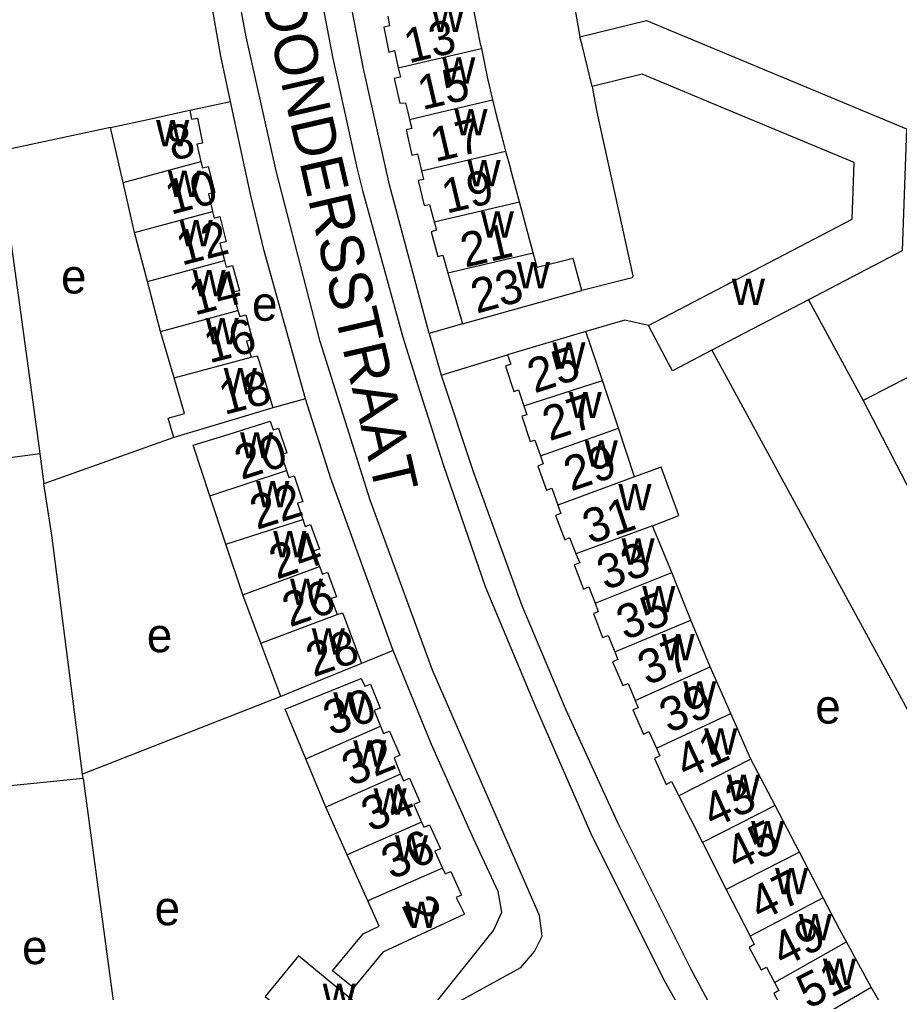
# Model space of a CAD drawing. Extents: x 161141 to 163125, y 381621 to 383200.
# Drawn here: x 162447 to 162549.8, y 382330.5 to 382444.2 of the extents above; entities that cross this region are included whole.
import ezdxf

# ---------------------------------------------------------------- set-up
doc = ezdxf.new("R2010")
doc.units = 0
for name, color, linetype in [('BLT_Basislijn', 7, 'Continuous'), ('BLT_Bebouwing', 7, 'Continuous'), ('BLT_Centroide', 7, 'Continuous'), ('BLT_Huisnummer', 7, 'Continuous'), ('BLT_Huisnummer_ tussenligend', 7, 'Continuous'), ('BLT_Onderverdeling_panden', 7, 'Continuous'), ('BLT_Straatnaam', 7, 'Continuous')]:
    doc.layers.add(name, color=color, linetype=linetype)

msp = doc.modelspace()

# ---------------------------------------------------------------- linework, layer by layer
at = {"layer": 'BLT_Basislijn'}
for p, q in [((162470.54, 382439.87), (162467.69, 382456.09)), ((162473.49, 382442.13), (162470.94, 382456.3)), ((162480.44, 382456.29), (162483.63, 382439.6)), ((162477.01, 382426.5), (162473.49, 382442.13)), ((162471.68, 382434.6), (162470.54, 382439.87)), ((162483.63, 382439.6), (162486.48, 382426.67)), ((162466.9, 382433.57), (162471.68, 382434.6)), ((162474.01, 382423.75), (162471.68, 382434.6)), ((162457.66, 382431.55), (162444.54, 382428.75)), ((162482.13, 382406.54), (162477.01, 382426.5)), ((162486.48, 382426.67), (162487.08, 382424.17)), ((162487.08, 382424.17), (162491.79, 382407.05)), ((162475.61, 382417.12), (162474.01, 382423.75)), ((162480.44, 382399.86), (162475.61, 382417.12)), ((162539.18, 382411.42), (162545.56, 382399.66)), ((162498.76, 382408.62), (162494.88, 382407.48)), ((162491.79, 382407.05), (162493.8, 382400.69)), ((162494.88, 382407.48), (162496.28, 382402.62)), ((162487.97, 382388.02), (162482.13, 382406.54)), ((162496.28, 382402.62), (162504.01, 382404.98)), ((162527.9, 382405.52), (162569.67, 382328.72)), ((162496.28, 382402.62), (162500, 382391.35)), ((162493.8, 382400.69), (162496.54, 382392.04)), ((162480.44, 382399.86), (162476.6, 382398.79)), ((162483.37, 382390.55), (162480.44, 382399.86)), ((162465.03, 382395.34), (162449.88, 382389.91)), ((162449.39, 382393.43), (162435.44, 382391.55)), ((162449.39, 382393.43), (162449.88, 382389.91)), ((162496.54, 382392.04), (162501.42, 382377.94)), ((162500, 382391.35), (162505.69, 382375.72)), ((162490.67, 382370.44), (162483.37, 382390.55)), ((162495.26, 382368.13), (162487.97, 382388.02)), ((162501.42, 382377.94), (162507.21, 382364.06)), ((162505.69, 382375.72), (162510.86, 382363.5)), ((162490.67, 382370.44), (162486.99, 382368.93)), ((162495.16, 382359.48), (162490.67, 382370.44)), ((162477.56, 382365.09), (162454.39, 382355.98)), ((162507.21, 382364.06), (162513.89, 382348.78)), ((162510.86, 382363.5), (162516.88, 382350.34)), ((162500, 382348.54), (162495.16, 382359.48)), ((162454.46, 382355.5), (162443.13, 382354.34)), ((162516.88, 382350.34), (162525.44, 382333.21)), ((162502.95, 382342.3), (162500, 382348.54)), ((162513.89, 382348.78), (162522.44, 382331.7)), ((162525.44, 382333.21), (162528.2, 382328.08)), ((162522.44, 382331.7), (162532.47, 382313.94))]:
    msp.add_line(p, q, dxfattribs=at)
for points in [[(162494.88, 382407.48), (162490.26, 382424.86), (162487.16, 382438.59), (162484.97, 382449.88), (162482.85, 382462.33), (162479.37, 382488.89), (162492.21, 382499.45), (162509.86, 382491.53)], [(162509.86, 382491.53), (162505.95, 382480.43), (162506, 382478.74), (162512.49, 382442.15)], [(162513.91, 382436.34), (162514.48, 382433.33), (162518.68, 382414.23), (162518.59, 382413.97), (162512.72, 382412.49)], [(162444.54, 382428.75), (162449.3, 382394.04), (162449.39, 382393.43)], [(162520.51, 382408.41), (162517.74, 382409.05), (162513.19, 382407.72)], [(162454.39, 382355.98), (162450.81, 382383.91), (162449.88, 382389.91)], [(162493.76, 382326.89), (162505.57, 382333.42), (162507.2, 382335.28), (162508.07, 382337.08), (162507.78, 382339.48), (162505.89, 382343.76), (162495.26, 382368.13)], [(162454.46, 382355.5), (162454.43, 382355.72), (162454.39, 382355.98)], [(162454.46, 382355.5), (162458.85, 382322.91), (162451.48, 382311.31)], [(162493.76, 382326.89), (162502.41, 382337.75), (162503.37, 382339.89), (162502.95, 382342.3)]]:
    msp.add_lwpolyline(points, dxfattribs=at)
at = {"layer": 'BLT_Bebouwing'}
for p, q in [((162500.91, 382441.14), (162500.98, 382440.79)), ((162502.27, 382434.77), (162502.62, 382433.33)), ((162459.12, 382425.13), (162457.66, 382431.55)), ((162503.8, 382428.8), (162504.38, 382426.74)), ((162505.43, 382422.85), (162504.38, 382426.74)), ((162507.04, 382416.9), (162505.43, 382422.85)), ((162461.96, 382413.57), (162460.46, 382419.28)), ((162550.15, 382417.15), (162539.18, 382411.42)), ((162497.06, 382414.55), (162498.76, 382408.62)), ((162463.49, 382407.7), (162461.96, 382413.57)), ((162539.18, 382411.42), (162527.9, 382405.52)), ((162465.07, 382402.3), (162463.49, 382407.7)), ((162513.19, 382407.72), (162504.01, 382404.98)), ((162515.11, 382402), (162513.19, 382407.72)), ((162555.87, 382405.01), (162545.56, 382399.66)), ((162474.96, 382404.34), (162476.6, 382398.79)), ((162516.98, 382396.41), (162515.11, 382402)), ((162518.88, 382390.72), (162516.98, 382396.41)), ((162471.13, 382382.86), (162469.25, 382388.52)), ((162523.24, 382379.55), (162520.95, 382385.01)), ((162473.1, 382376.93), (162471.13, 382382.86)), ((162525.46, 382373.99), (162523.24, 382379.55)), ((162475.23, 382371.29), (162473.1, 382376.93)), ((162484.97, 382374.28), (162486.99, 382368.93)), ((162527.69, 382368.54), (162525.46, 382373.99)), ((162477.56, 382365.09), (162475.23, 382371.29)), ((162532.47, 382357.75), (162530.11, 382363.08)), ((162482.79, 382352.15), (162480.46, 382357.79)), ((162524.03, 382353.47), (162526.81, 382348.01)), ((162538.14, 382346.88), (162535.31, 382352.32)), ((162526.81, 382348.01), (162529.58, 382342.54)), ((162540.91, 382341.56), (162538.14, 382346.88)), ((162487.71, 382341.2), (162485.3, 382346.57)), ((162529.58, 382342.54), (162532.36, 382337.07)), ((162546.52, 382331.1), (162543.62, 382336.42))]:
    msp.add_line(p, q, dxfattribs=at)
for points in [[(162500.91, 382441.14), (162499.95, 382446.06), (162499.79, 382446.85)], [(162490.03, 382444.55), (162490.25, 382443.42), (162489.57, 382443.28), (162490.18, 382440.36), (162490.81, 382440.53), (162491.27, 382438.51)], [(162512.49, 382442.15), (162520.27, 382444.05), (162545.96, 382433.33), (162550.65, 382431.38), (162550.15, 382417.15)], [(162513.91, 382436.34), (162512.74, 382441.16), (162512.49, 382442.15)], [(162500.98, 382440.79), (162501.7, 382437.29), (162502.27, 382434.77)], [(162491.27, 382438.51), (162491.51, 382437.42), (162490.8, 382437.27), (162491.46, 382434.38), (162492.12, 382434.44), (162492.39, 382433.33), (162492.59, 382432.49)], [(162520.51, 382408.41), (162544.3, 382420.85), (162544.53, 382427.45), (162530.41, 382433.33), (162519.77, 382437.77), (162513.91, 382436.34)], [(162457.66, 382431.55), (162462.01, 382432.5), (162465.83, 382433.33), (162466.9, 382433.57)], [(162466.9, 382433.57), (162466.94, 382433.33), (162467.1, 382432.54), (162467.8, 382432.64), (162468.4, 382429.73), (162467.72, 382429.59), (162468.21, 382427.59)], [(162502.62, 382433.33), (162503.51, 382429.87), (162503.8, 382428.8)], [(162492.59, 382432.49), (162492.85, 382431.42), (162492.18, 382431.27), (162492.85, 382428.33), (162493.5, 382428.49), (162493.97, 382426.49)], [(162468.21, 382427.59), (162468.4, 382426.82), (162469.05, 382427), (162469.82, 382423.95), (162469.08, 382423.78), (162469.57, 382421.74)], [(162493.97, 382426.49), (162494.2, 382425.49), (162493.58, 382425.34), (162494.31, 382422.43), (162494.9, 382422.57), (162495.47, 382420.51)], [(162460.46, 382419.28), (162459.12, 382425.13)], [(162469.57, 382421.74), (162469.75, 382420.96), (162470.43, 382421.15), (162471.18, 382418.18), (162470.44, 382418.03), (162470.97, 382415.99)], [(162495.47, 382420.51), (162495.73, 382419.54), (162495.1, 382419.37), (162495.9, 382416.48), (162496.47, 382416.65), (162497.06, 382414.55)], [(162512.72, 382412.49), (162511.69, 382416.24), (162507.49, 382415.21), (162507.04, 382416.9)], [(162470.97, 382415.99), (162471.16, 382415.24), (162471.91, 382415.41), (162472.7, 382412.47), (162471.95, 382412.29), (162472.54, 382410.16)], [(162498.76, 382408.62), (162500, 382408.96), (162512.72, 382412.49)], [(162472.54, 382410.16), (162472.74, 382409.45), (162473.44, 382409.66), (162474.24, 382406.7), (162473.54, 382406.57), (162474.07, 382404.73)], [(162527.9, 382405.52), (162523.29, 382403.1), (162522.83, 382403.98), (162520.51, 382408.41)], [(162474.07, 382404.73), (162474.8, 382404.87), (162474.96, 382404.34)], [(162504.01, 382404.98), (162504.4, 382403.88), (162503.8, 382403.66), (162504.77, 382400.7), (162505.32, 382400.88), (162505.94, 382399.02)], [(162465.03, 382395.34), (162464.37, 382397.6), (162466.28, 382398.15), (162465.07, 382402.3)], [(162505.94, 382399.02), (162506.28, 382397.99), (162505.71, 382397.83), (162506.68, 382394.87), (162507.24, 382395.03), (162507.88, 382393.2)], [(162545.56, 382399.66), (162553.32, 382384.69), (162551.06, 382383.52), (162555.05, 382375.82), (162557.29, 382376.98), (162570.82, 382350.91), (162569.14, 382350.04), (162575.86, 382337.08), (162579.21, 382338.82), (162580.68, 382335.99), (162581.34, 382335.17)], [(162476.6, 382398.79), (162471.81, 382397.36), (162465.03, 382395.34)], [(162469.25, 382388.52), (162467.29, 382394.42), (162471.53, 382395.71), (162476.3, 382397.23), (162476.65, 382396.24), (162477.27, 382396.42), (162478.24, 382393.55), (162477.6, 382393.3), (162478.21, 382391.47)], [(162507.88, 382393.2), (162508.21, 382392.24), (162507.59, 382392), (162508.6, 382389.18), (162509.2, 382389.4), (162509.9, 382387.41)], [(162478.21, 382391.47), (162478.48, 382390.67), (162479.11, 382390.87), (162480.11, 382387.82), (162479.49, 382387.64), (162480.13, 382385.75)], [(162520.95, 382385.01), (162524.05, 382386.2), (162523.69, 382387.18), (162521.98, 382391.88), (162518.88, 382390.72)], [(162509.9, 382387.41), (162510.24, 382386.47), (162509.65, 382386.21), (162510.73, 382383.38), (162511.27, 382383.64), (162512.03, 382381.73)], [(162480.13, 382385.75), (162480.4, 382384.93), (162481, 382385.17), (162482.06, 382382.3), (162481.41, 382382.09), (162482.08, 382380.27)], [(162512.03, 382381.73), (162512.46, 382380.67), (162511.83, 382380.47), (162512.9, 382377.62), (162513.52, 382377.9), (162514.26, 382375.96)], [(162482.08, 382380.27), (162482.41, 382379.37), (162483, 382379.58), (162484.07, 382376.72), (162483.42, 382376.51), (162484.12, 382374.67)], [(162514.26, 382375.96), (162514.63, 382374.98), (162514.06, 382374.77), (162515.13, 382371.95), (162515.77, 382372.2), (162516.57, 382370.28)], [(162484.12, 382374.67), (162484.76, 382374.83), (162484.97, 382374.28)], [(162516.57, 382370.28), (162516.93, 382369.41), (162516.28, 382369.12), (162517.49, 382366.34), (162518.14, 382366.57), (162518.93, 382364.62)], [(162486.99, 382368.93), (162482.36, 382367.05), (162477.56, 382365.09)], [(162530.11, 382363.08), (162527.69, 382368.54)], [(162480.46, 382357.79), (162478.05, 382363.6), (162482.31, 382365.32), (162486.95, 382367.17), (162487.36, 382366.28), (162488.01, 382366.52), (162489.15, 382363.7), (162488.45, 382363.43), (162489.2, 382361.61)], [(162518.93, 382364.62), (162519.31, 382363.76), (162518.66, 382363.52), (162519.9, 382360.66), (162520.54, 382360.98), (162521.43, 382359.02)], [(162489.2, 382361.61), (162489.56, 382360.75), (162490.23, 382361.01), (162491.44, 382358.21), (162490.77, 382357.89), (162491.54, 382355.98)], [(162521.43, 382359.02), (162521.84, 382358.15), (162521.21, 382357.84), (162522.58, 382354.8), (162523.19, 382355.13), (162524.03, 382353.47)], [(162535.31, 382352.32), (162532.47, 382357.75)], [(162491.54, 382355.98), (162491.86, 382355.2), (162492.57, 382355.53), (162493.77, 382352.78), (162493.09, 382352.44), (162494, 382350.38)], [(162485.3, 382346.57), (162482.79, 382352.15)], [(162494, 382350.38), (162494.26, 382349.79), (162494.93, 382350.06), (162496.2, 382347.26), (162495.53, 382346.99), (162496.45, 382345.02)], [(162496.45, 382345.02), (162496.76, 382344.35), (162497.4, 382344.62), (162498.65, 382341.85), (162498.03, 382341.6), (162498.99, 382339.63), (162489.46, 382335.2), (162486.02, 382331.02), (162483.59, 382333.02), (162487.17, 382337.35), (162489.05, 382338.23), (162487.71, 382341.2)], [(162543.62, 382336.42), (162542.82, 382337.88), (162540.91, 382341.56)], [(162532.36, 382337.07), (162532.86, 382336.09), (162532.26, 382335.75), (162533.67, 382333.12), (162534.27, 382333.45), (162535.22, 382331.65)], [(162485.25, 382322.14), (162489.17, 382326.89), (162484.77, 382330.52), (162479.62, 382334.77), (162475.7, 382330.01), (162477.87, 382328.22)], [(162535.22, 382331.65), (162535.71, 382330.71), (162535.15, 382330.36), (162536.13, 382328.6), (162536.72, 382328.91), (162538.22, 382326.31)], [(162549.58, 382325.79), (162546.52, 382331.1)]]:
    msp.add_lwpolyline(points, dxfattribs=at)
at = {"layer": 'BLT_Onderverdeling_panden'}
for p, q in [((162491.27, 382438.51), (162500.98, 382440.79)), ((162493.97, 382426.49), (162503.8, 382428.8)), ((162459.12, 382425.13), (162468.21, 382427.59)), ((162495.47, 382420.51), (162505.43, 382422.85)), ((162460.46, 382419.28), (162469.57, 382421.74)), ((162497.06, 382414.55), (162507.04, 382416.9)), ((162461.96, 382413.57), (162470.97, 382415.99)), ((162463.49, 382407.7), (162472.54, 382410.16)), ((162465.07, 382402.3), (162474.07, 382404.73)), ((162505.94, 382399.02), (162515.11, 382402)), ((162507.88, 382393.2), (162516.98, 382396.41)), ((162469.25, 382388.52), (162478.21, 382391.47)), ((162518.88, 382390.72), (162509.9, 382387.41)), ((162471.13, 382382.86), (162480.13, 382385.75)), ((162520.95, 382385.01), (162512.03, 382381.73)), ((162473.1, 382376.93), (162482.08, 382380.27)), ((162514.26, 382375.96), (162523.24, 382379.55)), ((162475.23, 382371.29), (162484.12, 382374.67)), ((162516.57, 382370.28), (162525.46, 382373.99)), ((162518.93, 382364.62), (162527.69, 382368.54)), ((162521.43, 382359.02), (162530.11, 382363.08)), ((162480.46, 382357.79), (162489.2, 382361.61)), ((162532.47, 382357.75), (162524.03, 382353.47)), ((162491.54, 382355.98), (162482.79, 382352.15)), ((162535.31, 382352.32), (162526.81, 382348.01)), ((162494, 382350.38), (162485.3, 382346.57)), ((162538.14, 382346.88), (162529.58, 382342.54)), ((162496.45, 382345.02), (162487.71, 382341.2)), ((162540.91, 382341.56), (162532.36, 382337.07)), ((162535.22, 382331.65), (162543.62, 382336.42)), ((162538.22, 382326.31), (162546.52, 382331.1))]:
    msp.add_line(p, q, dxfattribs=at)
msp.add_lwpolyline([(162492.59, 382432.49), (162496.17, 382433.33), (162502.27, 382434.77)], dxfattribs=at)

# ---------------------------------------------------------------- texts
at = {"layer": 'BLT_Centroide'}
for s, p in [('w', (162495.15, 382442.69)), ('w', (162496.4, 382436.66)), ('w', (162497.82, 382430.62)), ('w', (162462.97, 382429.34)), ('w', (162499.35, 382424.66)), ('w', (162464.34, 382423.44)), ('w', (162500.91, 382418.69)), ('w', (162465.72, 382417.66)), ('e', (162451.87, 382412.16)), ('w', (162467.24, 382411.84)), ('w', (162505.11, 382412.75)), ('w', (162530.24, 382410.81)), ('e', (162474.18, 382408.97)), ('w', (162468.77, 382406.22)), ('w', (162509.27, 382403.38)), ('w', (162470.88, 382400.38)), ('w', (162511.18, 382397.59)), ('w', (162472.78, 382392.88)), ('w', (162513.05, 382391.91)), ('w', (162474.67, 382387.16)), ('w', (162516.98, 382386.81)), ('w', (162476.66, 382381.34)), ('w', (162517.35, 382380.47)), ('w', (162478.62, 382375.78)), ('w', (162519.77, 382374.91)), ('e', (162461.89, 382370.24)), ('w', (162481.16, 382369.97)), ('w', (162522.03, 382369.31)), ('w', (162524.55, 382363.78)), ('w', (162483.68, 382362.47)), ('e', (162539.98, 382361.91)), ('w', (162527.01, 382358.28)), ('w', (162486, 382356.88)), ('w', (162529.67, 382352.88)), ('w', (162488.38, 382351.28)), ('w', (162532.48, 382347.44)), ('w', (162490.88, 382345.78)), ('w', (162535.28, 382341.97)), ('e', (162462.8, 382338.35)), ('w', (162492.06, 382338.03)), ('w', (162538.05, 382336.59)), ('e', (162447.32, 382333.8)), ('w', (162540.88, 382331.38)), ('w', (162482.44, 382328.44))]:
    msp.add_text(s, height=4, dxfattribs=at).set_placement(p)
at = {"layer": 'BLT_Huisnummer'}
for s, rotation, p in [('15', 13.2396, (162494.07, 382433.57)), ('8', 14.5759, (162464.9, 382427.61)), ('19', 13.2408, (162496.89, 382421.47)), ('12', 14.5723, (162465.96, 382415.4)), ('23', 15.4881, (162500.42, 382409.78)), ('16', 14.5725, (162469.19, 382403.98)), ('25', 18.3165, (162507.18, 382400.46)), ('20', 17.6412, (162472.94, 382390.35)), ('29', 18.5013, (162511.44, 382389.02)), ('24', 19.3009, (162477.08, 382378.7)), ('33', 20.8115, (162515.46, 382377.43)), ('28', 19.3006, (162481.37, 382367.3)), ('37', 22.7828, (162520.33, 382366.31)), ('41', 24.6795, (162524.85, 382355.37)), ('32', 22.0151, (162485.72, 382354.53)), ('45', 26.6666, (162530.8, 382344.6)), ('36', 24.9016, (162490.51, 382343.59)), ('2', 294.2163, (162491.59, 382340.69)), ('49', 26.6659, (162536.2, 382333.36))]:
    msp.add_text(s, height=4, rotation=rotation, dxfattribs=at).set_placement(p)
at = {"layer": 'BLT_Huisnummer_ tussenligend'}
for s, rotation, p in [('13', 13.2405, (162492.48, 382439.03)), ('17', 13.2396, (162495.57, 382427.49)), ('10', 14.5759, (162464.67, 382421.34)), ('21', 13.2408, (162499.08, 382415.17)), ('14', 14.5723, (162467.46, 382409.57)), ('18', 14.5725, (162470.94, 382397.95)), ('27', 18.3165, (162508.94, 382394.88)), ('22', 17.6412, (162474.73, 382384.52)), ('31', 18.5013, (162513.64, 382382.83)), ('26', 19.3009, (162478.6, 382373.13)), ('35', 20.8115, (162517.74, 382371.61)), ('30', 19.3006, (162483.39, 382360.46)), ('39', 22.7828, (162522.87, 382360.74)), ('34', 22.0151, (162487.99, 382349.2)), ('43', 24.6795, (162527.99, 382349.61)), ('47', 26.6666, (162533.57, 382338.77)), ('51', 26.6659, (162539.14, 382328.5))]:
    msp.add_text(s, height=4, rotation=rotation, dxfattribs=at).set_placement(p)
at = {"layer": 'BLT_Straatnaam'}
msp.add_text('PETRUS DONDERSSTRAAT', height=5, rotation=283.0411, dxfattribs=at).set_placement((162468.72, 382474.96))

doc.saveas('drawing.dxf')
